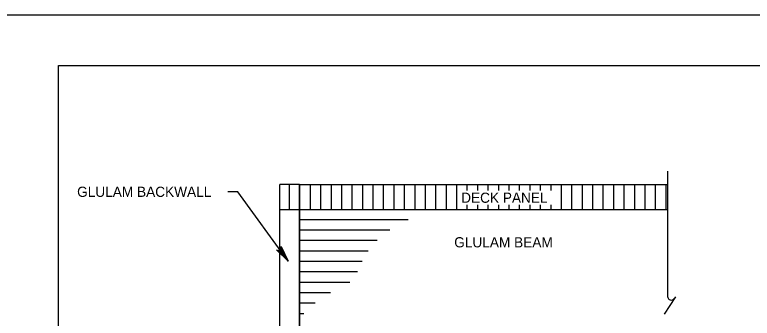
# Model space of a CAD drawing. Extents: x 638263 to 640360, y 293683 to 298655.
# Drawn here: x 639303.6 to 639520.4, y 298346 to 298435.5 of the extents above; entities that cross this region are included whole.
import ezdxf

# ---------------------------------------------------------------- set-up
doc = ezdxf.new("R2010")
doc.units = 0
for name, color, linetype in [('2', 7, 'Continuous'), ('3', 7, 'Continuous'), ('5', 7, 'Continuous'), ('7', 7, 'Continuous'), ('PLT-BNDY', 7, 'Continuous')]:
    doc.layers.add(name, color=color, linetype=linetype)

msp = doc.modelspace()

# ---------------------------------------------------------------- linework, layer by layer
at = {"layer": '2'}
for p, q in [((639316.46, 297856.46), (639316.46, 298420.46)), ((639316.46, 298420.46), (640102.46, 298420.46))]:
    msp.add_line(p, q, dxfattribs=at)
at = {"layer": '3'}
for p, q in [((639369.18, 298383.26), (639366.23, 298383.26)), ((639383.93, 298362.9), (639369.18, 298383.26))]:
    msp.add_line(p, q, dxfattribs=at)
msp.add_lwpolyline([(639383.93, 298362.9), (639380.49, 298366.16), (639380.9, 298366.01), (639381.26, 298366.05), (639381.55, 298366.19), (639381.77, 298366.41), (639381.91, 298366.75), (639381.9, 298367.18), (639383.93, 298362.9), (639381.91, 298366.75), (639381.77, 298366.41), (639383.93, 298362.9), (639381.55, 298366.19), (639381.26, 298366.05), (639383.93, 298362.9), (639380.9, 298366.01)], dxfattribs=at)
at = {"layer": '5'}
for p, q in [((639495.53, 298389.38), (639495.53, 298352.47)), ((639381.56, 298308.06), (639381.56, 298385.48)), ((639387.33, 298385.48), (639381.56, 298385.48)), ((639384.25, 298385.48), (639384.25, 298378.04)), ((639387.33, 298308.06), (639387.33, 298385.48)), ((639387.33, 298385.48), (639387.33, 298378.04)), ((639387.33, 298385.48), (639495.53, 298385.48)), ((639390.4, 298385.48), (639390.4, 298378.04)), ((639393.48, 298385.48), (639393.48, 298378.04)), ((639396.56, 298385.48), (639396.56, 298378.04)), ((639399.63, 298385.48), (639399.63, 298378.04)), ((639402.71, 298385.48), (639402.71, 298378.04)), ((639405.78, 298385.48), (639405.78, 298378.04)), ((639408.86, 298385.48), (639408.86, 298378.04)), ((639411.93, 298385.48), (639411.93, 298378.04)), ((639415.01, 298385.48), (639415.01, 298378.04)), ((639418.09, 298385.48), (639418.09, 298378.04)), ((639421.16, 298385.48), (639421.16, 298378.04)), ((639424.24, 298385.48), (639424.24, 298378.04)), ((639427.31, 298385.48), (639427.31, 298378.04)), ((639430.39, 298385.48), (639430.39, 298378.04)), ((639433.46, 298385.48), (639433.46, 298378.04)), ((639436.54, 298385.48), (639436.54, 298383.66)), ((639439.62, 298385.48), (639439.62, 298383.66)), ((639442.69, 298385.48), (639442.69, 298383.66)), ((639445.77, 298385.48), (639445.77, 298383.66)), ((639448.84, 298385.48), (639448.84, 298383.66)), ((639451.92, 298385.48), (639451.92, 298383.66)), ((639455, 298385.48), (639455, 298383.66)), ((639458.07, 298385.48), (639458.07, 298383.66)), ((639461.15, 298385.48), (639461.15, 298383.66)), ((639464.22, 298385.48), (639464.22, 298378.04)), ((639467.3, 298385.48), (639467.3, 298378.04)), ((639470.37, 298385.48), (639470.37, 298378.04)), ((639473.45, 298385.48), (639473.45, 298378.04)), ((639476.52, 298385.48), (639476.52, 298378.04)), ((639479.6, 298385.48), (639479.6, 298378.04)), ((639482.68, 298385.48), (639482.68, 298378.04)), ((639485.75, 298385.48), (639485.75, 298378.04)), ((639488.83, 298385.48), (639488.83, 298378.04)), ((639491.9, 298385.48), (639491.9, 298378.04)), ((639494.98, 298385.48), (639494.98, 298378.04)), ((639436.54, 298379.44), (639436.54, 298378.04)), ((639439.62, 298379.44), (639439.62, 298378.04)), ((639442.69, 298379.44), (639442.69, 298378.04)), ((639445.77, 298379.44), (639445.77, 298378.04)), ((639448.84, 298379.44), (639448.84, 298378.04)), ((639451.92, 298379.44), (639451.92, 298378.04)), ((639455, 298379.44), (639455, 298378.04)), ((639458.07, 298379.44), (639458.07, 298378.04)), ((639461.15, 298379.44), (639461.15, 298378.04)), ((639381.56, 298378.04), (639495.53, 298378.04)), ((639387.33, 298378.04), (639387.33, 298308.06)), ((639497.8, 298352.39), (639494.54, 298347.21))]:
    msp.add_line(p, q, dxfattribs=at)
msp.add_arc((639496.59, 298352.47), 1.07, 180, 330, dxfattribs=at)
at = {"layer": '7'}
for p, q in [((639387.33, 298375.17), (639419.21, 298375.17)), ((639387.33, 298372.1), (639413.87, 298372.1)), ((639387.33, 298369.02), (639410.11, 298369.02)), ((639387.33, 298365.94), (639407.49, 298365.94)), ((639387.33, 298362.87), (639405.71, 298362.87)), ((639387.33, 298359.79), (639404.32, 298359.79)), ((639387.33, 298356.72), (639402.1, 298356.72)), ((639387.33, 298353.64), (639396.41, 298353.64)), ((639387.33, 298350.56), (639391.9, 298350.56)), ((639387.33, 298347.49), (639388.54, 298347.49))]:
    msp.add_line(p, q, dxfattribs=at)
at = {"layer": 'PLT-BNDY'}
msp.add_lwpolyline([(639276.46, 298435.46), (640117.46, 298435.46), (640117.46, 297841.46), (639276.46, 297841.46)], close=True, dxfattribs=at)

# ---------------------------------------------------------------- texts
at = {"layer": '3'}
for s, p in [('GLULAM BACKWALL', (639321.91, 298381.8)), ('DECK PANEL', (639434.82, 298380.05)), ('GLULAM BEAM', (639432.78, 298366.93))]:
    msp.add_text(s, height=3, dxfattribs=at).set_placement(p)

doc.saveas('drawing.dxf')
